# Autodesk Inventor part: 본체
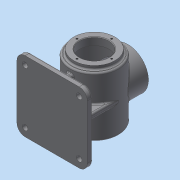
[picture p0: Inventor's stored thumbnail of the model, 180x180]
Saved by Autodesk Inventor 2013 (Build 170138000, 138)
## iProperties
Created: 2015-07
Part Number: 본체
Material: 일반
Document SubType Name: Modeling
Designer: Administrator
Density: 1 g/cm^3
Author: Administrator
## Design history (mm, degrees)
sketch "스케치1"
  geometry: C1 r 45 at (0, 0); 1 further point
  constraints: 1 centre point, 1 coincident
  dimensions: "d0" = 90 diameter of C1
extrude "돌출1" new body sketch "스케치1" stored distance "d1" = 110; taper "d2" = 0 deg
sketch "스케치2"
  geometry: C1 r 45 at (0, 0) reference; C2 r 38 at (0, 0)
  constraints: 1 centre point, 1 coincident
  dimensions: "d3" = 76 diameter of C2
extrude "돌출2" join sketch "스케치2" distance "d4" = 7; taper "d5" = 0 deg
sketch "스케치3"
  geometry: C1 r 38 at (0, 0) reference; C2 r 27 at (0, 0)
  constraints: 1 centre point, 1 coincident
  dimensions: "d6" = 54 diameter of C2
extrude "돌출3" cut sketch "스케치3" distance "d7" = 14; taper "d8" = 0 deg
sketch "스케치4"
  geometry: C1 r 27 at (0, 0) reference; C2 r 40 at (0, 0)
  constraints: 1 centre point, 1 coincident
  dimensions: "d9" = 80 diameter of C2
extrude "돌출4" cut sketch "스케치4" distance "d10" = 96; taper "d11" = 0 deg
node "작업 평면1"
sketch "스케치5"
  geometry: L1 (-65, 65)-(65, 65); L2 (65, 65)-(65, -65); L3 (65, -65)-(-65, -65); L4 (-65, -65)-(-65, 65); L5 (-65, 65)-(65, -65); L6 (65, 65)-(-65, -65); 1 further point
  constraints: 12 end point, 2 midpoint, 2 parallel, 1 horizontal, 1 perpendicular
  dimensions: "d13" = 130 distance of L2.end L3.end; "d14" = 130 distance of L1.end L2.end
extrude "돌출5" join sketch "스케치5" distance "d15" = 10; taper "d16" = 0 deg
sketch "스케치6"
  geometry: L1 (-50, -50)-(50, -50); L2 (50, -50)-(50, 50); L3 (50, 50)-(-50, 50); L4 (-50, 50)-(-50, -50); L5 (-50, -50)-(50, 50); L6 (50, -50)-(-50, 50); C1 r 7.5 at (-50, 50); C2 r 7.5 at (50, 50); C3 r 7.5 at (50, -50); C4 r 7.5 at (-50, -50); 1 further point
  constraints: 12 end point, 4 centre point, 4 coincident, 2 midpoint, 2 parallel, 1 horizontal, 1 perpendicular
  dimensions: "d17" = 100 distance of L3.end L2.end; "d18" = 100 distance of L2.end L1.end; "d19" = 15 diameter of C1; "d20" = 15 diameter of C2; "d21" = 15 diameter of C3; "d22" = 15 diameter of C4
extrude "돌출6" join sketch "스케치6" distance "d23" = 3; taper "d24" = 0 deg
sketch "스케치7"
  geometry: C1 r 7.5 at (0, -100) reference; C2 r 7.5 at (-100, 0) reference; C3 r 7.5 at (0, 0) reference; C4 r 7.5 at (-100, -100) reference; C5 r 5 at (-100, 0); C6 r 5 at (0, 0); C7 r 5 at (0, -100); C8 r 5 at (-100, -100); 1 further point
  constraints: 4 centre point, 4 coincident
  dimensions: "d25" = 10 diameter of C5; "d26" = 10 diameter of C6; "d27" = 10 diameter of C7; "d28" = 10 diameter of C8
extrude "돌출7" cut sketch "스케치7" stored distance "d29" = 3; taper "d30" = 0 deg
node "작업 평면2"
sketch "스케치8"
  geometry: C1 r 38 at (0, 0); 1 further point
  constraints: 1 centre point, 1 coincident
  dimensions: "d32" = 76 diameter of C1
extrude "돌출8" join sketch "스케치8" stored distance "d33" = 3; taper "d34" = 0 deg
sketch "스케치9"
  geometry: C1 r 38 at (0, 0) reference; C2 r 27 at (0, 0)
  constraints: 1 centre point, 1 coincident
  dimensions: "d35" = 54 diameter of C2
extrude "돌출9" cut sketch "스케치9" stored distance "d36" = 3; taper "d37" = 0 deg
sketch "스케치10"
  geometry: C1 r 27 at (0, 0) reference; 1 further point
  constraints: 1 vertical alignment
  dimensions: "d38" = 32 distance of point (0, 32) C1.centre
hole "구멍1" sketch "스케치10" at (0, 32) diameter "d39" = 3.242; stored, may be unused: countersink angle "d43" = 90 deg, drill point angle "d45" = 118 deg; dims "d40" = 8, "d41" = 4, "d42" = 2, "d44" = 10
sketch "스케치11"
  geometry: C1 r 27 at (0, 0) reference; 1 further point
  constraints: 1 vertical alignment
  dimensions: "d49" = 32 distance of point (0, 32) C1.centre
hole "구멍2" sketch "스케치11" at (0, 32) diameter "d50" = 3.242; stored, may be unused: countersink angle "d54" = 90 deg, drill point angle "d56" = 118 deg; dims "d51" = 8, "d52" = 4, "d53" = 2, "d55" = 10
sketch "스케치12"
  geometry: L1 (-65, 65)-(-65, -65) reference; L2 (-5, 5)-(-5, 45); L3 (-5, 45)-(5, 45); L4 (5, 45)-(5, 5); L5 (5, 5)-(45, 5); L6 (45, 5)-(45, -5); L7 (45, -5)-(5, -5); L8 (5, -5)-(5, -45); L9 (5, -45)-(-5, -45); L10 (-5, -45)-(-5, -5); L11 (-5, -5)-(-45, -5); L12 (-45, -5)-(-45, 5); L13 (-45, 5)-(-5, 5); 5 further points
  constraints: 24 end point, 10 parallel, 5 equal length, 4 midpoint, 2 horizontal alignment, 2 vertical alignment, 1 collinear, 1 perpendicular
  dimensions: "d60" = 10 distance of L2.end L3.end; "d62" = 10 distance of L5.end L6.end; "d63" = 45 distance from line of L3 point (0, 0)
extrude "돌출10" join sketch "스케치12" stored distance "d64" = 3; taper "d65" = 0 deg
sketch "스케치13"
  geometry: C1 r 45 at (0, 0) reference; 1 further point
  constraints: 2 coincident, 1 other
feature "엠보싱1" sketch "스케치13" dims "d1" = 110, "d2" = 0, "d66" = 0.5, "d67" = 0
fillet "모깎기1" dims "d68" = 3
fillet "모깎기3" dims "d70" = 15
fillet "모깎기2" dims "d69" = 3
chamfer "모따기1" distance "d71" = 1; stored, may be unused: second distance "d72" = 2, angle "d73" = 45 deg
node "솔리드1"
pattern_circular "원형 패턴1" dims angle "d47" = 360 deg
pattern_circular "원형 패턴2" dims angle "d58" = 360 deg
node "절단 모서리 투영1"
other parameters: "d12" = -78
